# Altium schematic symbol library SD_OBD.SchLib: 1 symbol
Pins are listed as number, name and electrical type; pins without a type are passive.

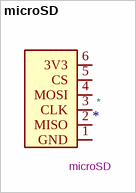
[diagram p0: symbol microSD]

## microSD
designator *  Reference: microSD
pins: 1 GND, 2 MISO, 3 CLK, 4 MOSI, 5 CS, 6 3V3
